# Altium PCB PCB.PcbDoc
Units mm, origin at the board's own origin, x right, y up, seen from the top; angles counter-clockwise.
Board outline 41 x 25.36 mm, 2 copper layers (TOP, BOTTOM), stack 1.586 mm thick; 29 components, 6 nets, 59 pads, 21 vias.
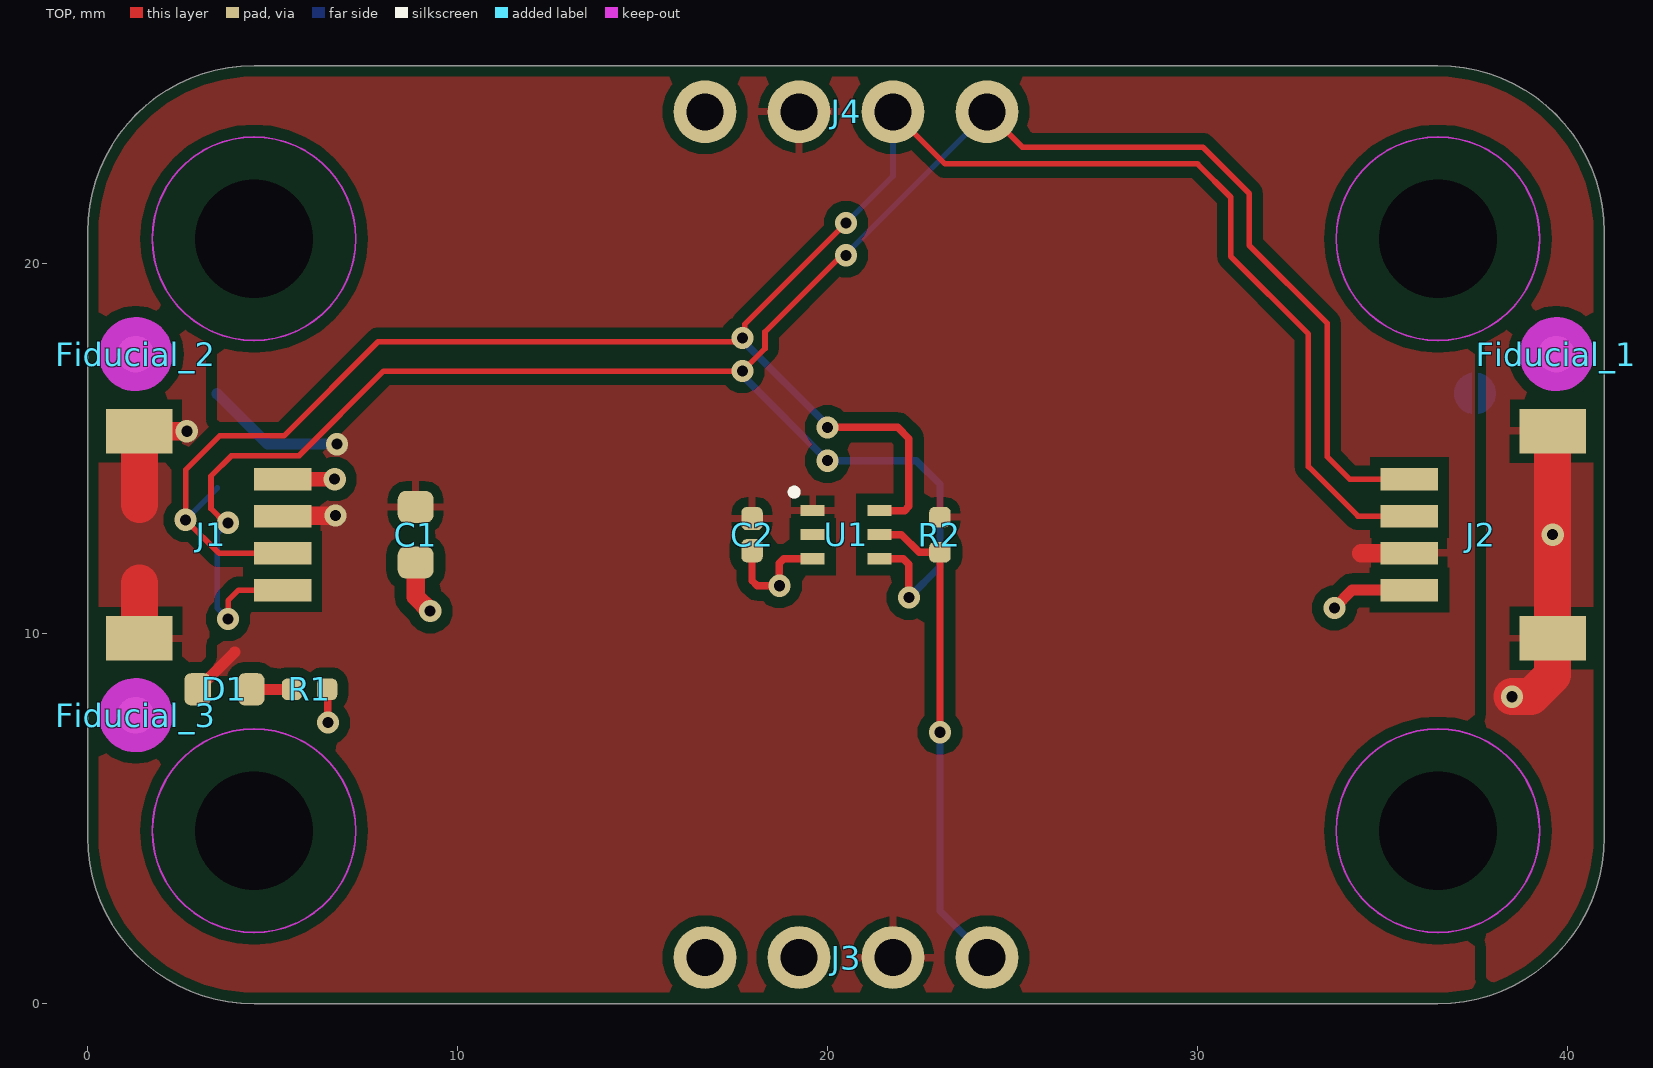
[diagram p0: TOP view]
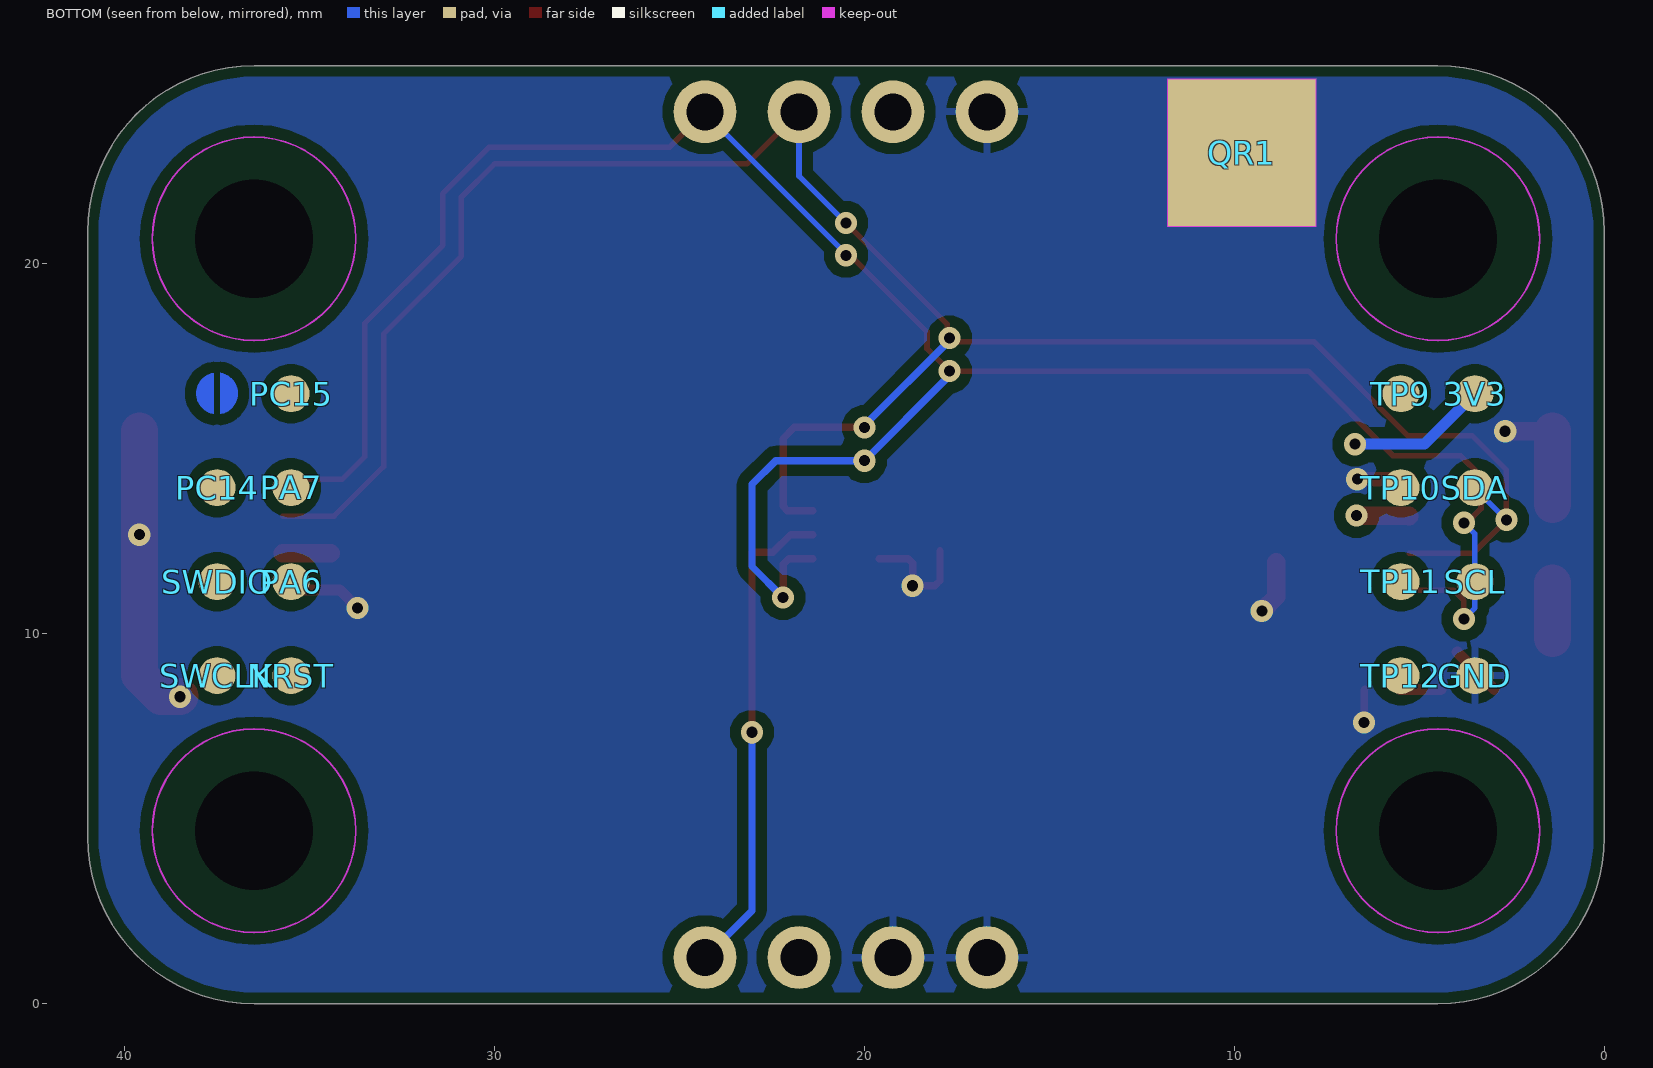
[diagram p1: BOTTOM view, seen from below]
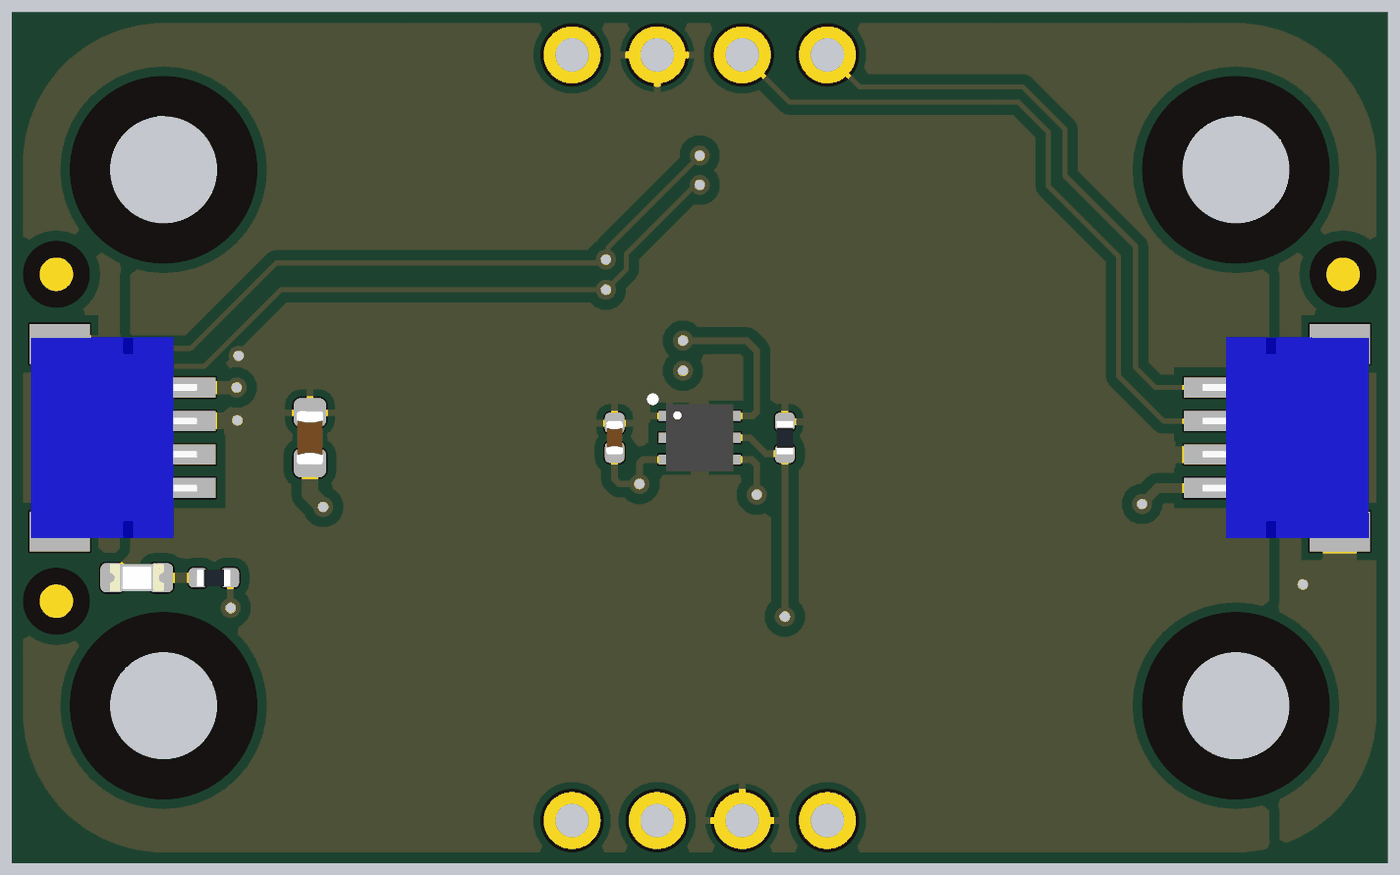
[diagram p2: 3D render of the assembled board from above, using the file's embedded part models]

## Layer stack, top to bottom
Top Solder: solder mask 0.01, Solder Resist, Dk 3.5
TOP: signal copper 0.018
Dielectric: core 1.55, FR-4, Dk 4.8
BOTTOM: signal copper 0.018
Bottom Solder: solder mask 0.01, Solder Resist, Dk 3.5

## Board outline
0,4.5 ccw(c4.5,4.5) 4.5,0 36.5,0 ccw(c36.5,4.5) 41,4.5 41,20.86 ccw(c36.5,20.86) 36.5,25.36 4.5,25.36 ccw(c4.5,20.86) 0,20.86

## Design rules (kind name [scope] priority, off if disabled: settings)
BoardOutlineClearance Mousebites [(ObjectKind = 'Pad') And (Name = 'Free-MOUSEBITE')] p1: gap=0 ignorepadtopadclearanceinfootprint=FALSE
BoardOutlineClearance Silks [(OnLayer('Top Overlay') OR OnLayer('Bottom Overlay'))] p2: gap=0 ignorepadtopadclearanceinfootprint=FALSE
BoardOutlineClearance [All] p3: gap=0.3 ignorepadtopadclearanceinfootprint=FALSE
Clearance COPPER_0.3mm [All] p1: gap=0.127 ignorepadtopadclearanceinfootprint=FALSE except(0.3: Arc-Fill Arc-Poly Arc-Region Track-Fill Track-Poly Track-Region SMDPad-Fill SMDPad-Poly SMDPad-Region THPad-Fill THPad-Poly THPad-Region Via-Fill Via-Poly Via-Region Fill-Fill Fill-Poly Fill-Region Poly-Poly Poly-Region Region-Region)
Clearance "Generic clearance 0.15mm" [All] p2: gap=0.127 ignorepadtopadclearanceinfootprint=FALSE
ComponentClearance [All] p1: gap=0.2 collisioncheckmode=3 verticalgap=0 showdistances=TRUE
DiffPairsRouting USB [InDifferentialPairClass('USB')] p1: maxlimit=0.15 minlimit=0.15 mostfreqgap=0.15 toplayer_minwidth=0.15 toplayer_maxwidth=0.21 toplayer_prefwidth=0.2 bottomlayer_minwidth=0.15 bottomlayer_maxwidth=0.21 bottomlayer_prefwidth=0.2 impedanceprofiledriven=TRUE impedanceprofileid={E6B00C31-4C8E-439C-824F-D2B2CDC26F9C} impedanceprofilevalue=90.000000 maxuncoupledlength=12.7
Height [All] p1: minheight=0 maxheight=30 prefheight=12.7
HoleSize [All] p1: absolutevalues=TRUE maxlimit=30 minlimit=0.3 maxpercent=80.000 minpercent=20.000
HoleToHoleClearance [All] p1: gap=0.25 allowstackedmicrovias=FALSE
MinimumAnnularRing [All] p1: minimumring=0.15
NetAntennae NetAntennae_1 [WithinRoom('SHORTROOM')] p1: netantennaetolerance=3
NetAntennae [All] p2: netantennaetolerance=0
PlaneConnect [All] p1: pad.planeconnectstyle=Relief pad.reliefexpansion=0.508 pad.reliefentries=4 pad.reliefconductorwidth=0.254 pad.reliefairgap=0.254 via.planeconnectstyle=Direct via.reliefexpansion=0.508 via.reliefentries=4 via.reliefconductorwidth=0.254 via.reliefairgap=0.254
PolygonConnect PolygonConnect_QR [(ObjectKind = 'Pad') And (Name = 'QR1-PAD')] p1: connectstyle=Direct reliefconductorwidth=0.254 reliefentries=4 polygonreliefangle="90 Angle" airgapwidth=0.254
PolygonConnect [All] p2: thpad.connectstyle=Relief thpad.reliefconductorwidth=0.2 thpad.reliefentries=4 thpad.polygonreliefangle="90 Angle" thpad.airgapwidth=0.254 smdpad.connectstyle=Relief smdpad.reliefconductorwidth=0.2 smdpad.reliefentries=4 smdpad.polygonreliefangle="90 Angle" smdpad.airgapwidth=0.254 via.connectstyle=Direct via.reliefconductorwidth=0.254 via.reliefentries=4 via.polygonreliefangle="90 Angle" via.airgapwidth=0.254
RoomDefinition SHORTROOM [False vs False] p1: confinementstyle=ConfineIn formatcopy=TRUE lockcomponents=FALSE outline 21.37,5.005 22.17,5.005 22.17,2.905 21.37,2.905
RoomDefinition K36 [False vs False] p2: confinementstyle=ConfineIn formatcopy=TRUE lockcomponents=FALSE outline 12.1,25.6 15.4,25.6 15.4,22.8 12.1,22.8
RoomDefinition U_MICROCONTROLLER [InComponentClass('U_MICROCONTROLLER')] p3: confinementstyle=ConfineIn formatcopy=TRUE lockcomponents=FALSE outline -26.2,-22.88 24.6,-22.88 24.6,2.52 -26.2,2.52
RoomDefinition TOP [InComponentClass('TOP')] p4: confinementstyle=ConfineIn formatcopy=TRUE lockcomponents=FALSE outline -26.2,-22.88 24.6,-22.88 24.6,2.52 -26.2,2.52
RoutingVias StandardVias [All] p1: holewidth=0.3 width=0.6 viastyle="Through Hole" minholewidth=0.3 minwidth=0.6 maxholewidth=0.3 maxwidth=0.6
SMDToCorner [All] p1: distance=39370
ShortCircuit Shortjumper [WithinRoom('SHORTROOM') vs WithinRoom('SHORTROOM')] p1: allowed=TRUE
ShortCircuit [All] p2: allowed=FALSE
SilkToSilkClearance [All] p1: silktosilkclearance=0.2
SilkToSolderMaskClearance [IsPad] p1: minsilkscreentomaskgap=0.15 clearancetoexposedcopper=TRUE
SolderMaskExpansion VIAtented [IsVia] p1: expansion=0.102 istentingtop=TRUE
SolderMaskExpansion [All] p2: expansion=0.05 istentingtop=FALSE
SupplyNets "Schematic Supply Nets_1" [InNet('GND')] p1: voltage=0.000
SupplyNets "Schematic Supply Nets" [InNet('+3V3')] p2: voltage=0.000
UnConnectedPin [All] p1:
UnRoutedNet [NOT WithinRoom('K36')] p1: checkbadconnections=TRUE
ViasUnderSMD [All] p1: allowed=FALSE
Width StandardTraces [All] p1: maxlimit=5 minlimit=0.15 preferedwidth=0.15 minimp=50.000000 maximp=50.000000 favimp=50.000000
19 further rules are at their usual default settings.

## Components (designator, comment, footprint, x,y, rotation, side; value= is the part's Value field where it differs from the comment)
3V3 "Test point 1.00mm" TP-1.00MM 3.5,16.49 r90 bottom
C1 "GRM188R61C475KAAJD" CAP-0603 8.868,12.68 r90 top value=4.7µF
C2 "0402B104K160CT" CAP-0402 17.96,12.68 r270 top value=100nF
D1 "HSMG-C190" LEDC1608X80N-AK 3.7,8.5 r180 top
Fiducial_1 "Fiducial mark 1mm" "Fiducial mark 1mm-Footprint-1" 39.7,17.56 r270 top
Fiducial_2 "Fiducial mark 1mm" "Fiducial mark 1mm-Footprint-1" 1.3,17.56 r270 top
Fiducial_3 "Fiducial mark 1mm" "Fiducial mark 1mm-Footprint-1" 1.3,7.8 r270 top
GND "Test point 1.00mm" TP-1.00MM 3.5,8.87 r90 bottom
J1 "SM04B-SRSS-TB(LF)(SN)" SM04B-SRSS-TB(LF)(SN)-Footprint-1 3.337,12.68 r90 top locked
J2 "SM04B-SRSS-TB(LF)(SN)" SM04B-SRSS-TB(LF)(SN)-Footprint-1 37.663,12.68 r270 top locked
J3 "HEADER TH 2.54mm VERT. 1x004POS" "PIN HEADER 2.54mm VERT. 1x4POS-Footprint-1" 20.5,1.25 r0 top
J4 "HEADER TH 2.54mm VERT. 1x004POS" "PIN HEADER 2.54mm VERT. 1x4POS-Footprint-1" 20.5,24.11 r0 top
NRST "Test point 1.00mm" TP-1.00MM 35.5,8.87 r180 bottom
PA6 "Test point 1.00mm" TP-1.00MM 35.5,11.41 r180 bottom
PA7 "Test point 1.00mm" TP-1.00MM 35.5,13.95 r180 bottom
PC14 "Test point 1.00mm" TP-1.00MM 37.5,13.95 r180 bottom
PC15 "Test point 1.00mm" TP-1.00MM 35.5,16.49 r180 bottom
QR1 "QR CODE 4x4mm" "QR CODE 4x4mm" 9.8,23 r180 bottom
R1 "CRCW04021K00FKEDC" RES-0402 6,8.5 r180 top value=1k
R2 "CRCW040210K0FKED" RES-0402 23.04,12.68 r270 top value=10k
SCL "Test point 1.00mm" TP-1.00MM 3.5,11.41 r90 bottom
SDA "Test point 1.00mm" TP-1.00MM 3.5,13.95 r90 bottom
SWCLK "Test point 1.00mm" TP-1.00MM 37.5,8.87 r180 bottom
SWDIO "Test point 1.00mm" TP-1.00MM 37.5,11.41 r180 bottom
TP9 "Test point 1.00mm" TP-1.00MM 5.5,16.49 r0 bottom
TP10 "Test point 1.00mm" TP-1.00MM 5.5,13.95 r0 bottom
TP11 "Test point 1.00mm" TP-1.00MM 5.5,11.41 r0 bottom
TP12 "Test point 1.00mm" TP-1.00MM 5.5,8.87 r0 bottom
U1 "LTR-381RGB-01" SON65P200X70-6N 20.5,12.68 r0 top

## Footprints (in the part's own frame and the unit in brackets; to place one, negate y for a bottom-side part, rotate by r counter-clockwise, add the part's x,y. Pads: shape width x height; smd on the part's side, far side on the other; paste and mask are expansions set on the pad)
CAP-0402 [mm] "Chip Capacitor, 2-Leads, Body  0402 (in) 1005 (mm), IPC Medium Density"
  rrect52% 0.63x0.58 smd mask+0.05: 1(-0.435,0) 2(0.435,0)
  body extent -0.5,-0.25 0.5,0.25, height 0.5
CAP-0603 [mm] "Chip Capacitor, Body 0603 imperial,1.6x0.8mm, IPC High Density"
  rrect51% 0.87x0.97 smd mask+0.05: 1(-0.75,0) 2(0.75,0)
  body extent -0.8,-0.4 0.8,0.4, height 0.8
"Fiducial mark 1mm-Footprint-1" [mm]
  round 1 smd paste-10 mask+0.5: 1(0,0)
  TOP keep-out circle w1: c0,0 r0.5
LEDC1608X80N-AK [mm]
  rrect50% 0.72x0.87 smd: A(0.725,0) C(-0.725,0)
  body extent -0.8,-0.4 0.8,0.4, height 0.79
"PIN HEADER 2.54mm VERT. 1x4POS-Footprint-1" [mm]
  round 1.7 hole 1 mask+0.1: 1(-3.81,0) 2(-1.27,0) 3(1.27,0) 4(3.81,0)
"QR CODE 4x4mm" [mm]
  rect 4x4 smd paste-2539.97 mask+0.1: PAD(0,0)
  TOP keep-out region: -2,2 2,2 2,-2 -2,-2
RES-0402 [mm] "Chip Resistor, 2-Leads, Body  0402 (in) 1005 (mm), IPC Medium Density"
  rrect51% 0.55x0.58 smd mask+0.05: 1(-0.475,0) 2(0.475,0)
  body extent -0.5,-0.25 0.5,0.25, height 0.34
SM04B-SRSS-TB(LF)(SN)-Footprint-1 [mm]
  rect 0.6x1.55 smd mask+0.05: 1(1.5,-1.937) 2(0.5,-1.937) 3(-0.5,-1.937) 4(-1.5,-1.937)
  rect 1.2x1.8 smd mask+0.05: FIX(-2.8,1.938) FIX(2.8,1.938)
  body extent -3,-2.16 3,2.8, height 2.98
SON65P200X70-6N [mm] "SON, 6-Leads, Body 2,00x2,00mm, Pitch 0,65mm, IPC Medium Density"
  rect 0.65x0.3 smd mask+0.05: 1(-0.9,0.65) 2(-0.9,0) 3(-0.9,-0.65) 4(0.9,-0.65) 5(0.9,0) 6(0.9,0.65)
  silkscreen extent -1.45,1.1 -1.35,1.2, body extent -1,-1 1,1, height 0.7
TP-1.00MM [mm]
  rrect100% 1x1 smd paste-2.54: X(0,0)

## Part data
3V3 GND NRST PA6 PA7 PC14 PC15 SCL SDA SWCLK SWDIO TP9 TP10 TP11 TP12: library part UT0013-A.6, Manufacturer="This is not a component"
C1: library part C0054-A.16, "CAP CHIP 0603 4.7uF 10% 16V X5R", Case Code (Imperial)=0603, Dielectric=X5R, Manufacturer=Murata, Manufacturer 3="Samsung Electro-Mechanics", Part number 2=GRM188R61C475KE11D, Part number 3=CL10A475KO8NNNC, Tolerance=10%, Voltage=16V
C2: library part C0012-A.15, "CAP CHIP 0402 100nF 10% 16V X7R", Case Code (Imperial)=0402, Dielectric=X7R, Manufacturer=Walsin, Tolerance=10%, Voltage=16V
D1: library part L0009-A.5, "LED SMD 0603 GREEN/568 15mcd 120^", Manufacturer=Broadcom
Fiducial_1 Fiducial_2 Fiducial_3: library part UT0023-A.7, "Fiducial mark 1mm clearance 2mm"
J1 J2: library part J0005-A.2, "CONN JST 4POS SIDE 1MM TIN QWIIC", Manufacturer=JST
J3 J4: library part J0162-A.6
QR1: library part QR-0001-A.5, "QR CODE 4x4mm on layer 34 (This is not a component)", Manufacturer="This is not a component"
R1: library part R0007-A.24, "RES CHIP 0402 1k 1% 1/16W", Case Code (Imperial)=0402, Manufacturer=Vishay, Power=62.5mW, Temperature Coefficient=100ppm, Tolerance=1%
R2: library part R0003-A.24, "RES CHIP 0402 10k 1% 1/16W", Case Code (Imperial)=0402, Manufacturer=Vishay, Power=62.5mW, Temperature Coefficient=100ppm, Tolerance=1%
U1: library part U0407-A.2, "IC light + RGB sensor , I2C, Vdd 1.7V to 3.6V, DFN 2x2mm", Manufacturer=Liteon

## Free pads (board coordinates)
  round 3 hole 3.2 unplated paste-2539.97 mask+1.3: MH(4.5,4.68) MH(4.5,20.68) MH(36.5,4.68) MH(36.5,20.68)

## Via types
v1: diameter 0.6, hole 0.3, TOP to BOTTOM, tented both sides, 21 vias

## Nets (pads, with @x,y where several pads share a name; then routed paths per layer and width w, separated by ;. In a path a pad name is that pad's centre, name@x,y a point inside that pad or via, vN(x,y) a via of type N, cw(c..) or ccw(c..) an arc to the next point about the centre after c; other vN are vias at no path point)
+3V3: 3V3.X C1.2 C2.1 D1.A J1.2 J2.2 J3.3 J4.2 R2.1 U1.1 | length 8
  TOP w0.3: D1.A 3.98,9.505
  TOP w0.5: J1.2 5.284,13.19 6.69,13.19 v1(6.7,13.2) ; 34.42,12.18 J2.2
  BOTTOM w0.3: 3V3.X 4.864,15.126 v1(6.741,15.126)
GND: C1.1 C2.2 GND.X J1.1 J1.FIX J2.1 J2.FIX J3.1 J3.2 J4.1 QR1.PAD R1.1 U1.3 | length 21.9
  TOP w0.2: R1.1 6.488,8.488 6.488,7.612 v1(6.5,7.6) ; C2.2 17.96,11.44 18.1,11.3 v1(18.7,11.3) 18.7,11.913 18.817,12.03 U1.3
  TOP w0.3: v1(33.7,10.7) 34.18,11.18 J2.1 J2.1@35.72,11.185
  TOP w0.4: J1.1 v1(6.68,14.18)
  TOP w0.5: J1.FIX@1.399,15.48 2.678,15.48 v1(2.683,15.475) ; C1.1 8.868,11.007 v1(9.261,10.613)
  TOP w1: J1.FIX@1.399,9.88 1.399,11.379 ; 1.399,13.499 J1.FIX@1.399,15.48 ; v1(38.5,8.3) 39.015,8.3 39.601,8.886 J2.FIX@39.601,9.88 ; J2.FIX@39.6,9.881 J2.FIX@39.6,15.48
  other v1: 39.6,12.68
INT_1: J3.4 R2.2 U1.5 | length 13.3
  TOP w0.2: U1.5 22,12.68 22.475,12.205 R2.2 v1(23.04,7.34)
  BOTTOM w0.2: v1(23.04,7.34) 23.04,2.52 J3.4
NetD1_C: D1.C R1.2 | length 1.1
  TOP w0.3: D1.C R1.2
SCL_1: J1.4 J2.4 J4.4 SCL.X U1.4 | length 62.1
  TOP w0.15: v1(3.8,10.4) 3.8,10.9 4.08,11.18 J1.4 ; v1(3.8,13) 3.723,13 3.337,13.386 3.337,14.262 3.888,14.813 5.718,14.813 8.005,17.1 v1(17.7,17.1) 18.31,17.71 18.31,18.162 20.378,20.23 v1(20.5,20.23) ; J4.4 25.263,23.157 30.143,23.157 31.4,21.9 31.4,20.5 33.502,18.398 33.502,14.788 34.11,14.18 J2.4
  TOP w0.2: U1.4 22.05,12.03 22.2,11.88 v1(22.2,10.98)
  BOTTOM w0.15: v1(3.8,10.4) 3.5,10.7 3.5,12.7 v1(3.8,13) ; v1(20.5,20.23) 20.5,20.265 24.31,24.075 J4.4
  BOTTOM w0.2: v1(17.7,17.1) 17.777,17.023 17.777,16.904 v1(20,14.68) 22.4,14.68 23.04,14.04 23.04,11.82 v1(22.2,10.98)
SDA_1: J1.3 J2.3 J4.3 SDA.X U1.6 | length 59.8
  TOP w0.15: 2.65,14.44 v1(2.65,13.082) 3.554,12.178 3.895,12.178 3.897,12.18 J1.3 ; 2.66,14.44 3.569,15.349 5.306,15.349 7.857,17.9 v1@17.7,17.9 ; v1@17.7,17.991 17.768,18.058 17.768,18.373 v1(20.5,21.105) ; J4.3 23.18,22.7 30,22.7 30.9,21.8 30.9,20.2 33,18.1 33,14.518 34.338,13.18 J2.3
  TOP w0.2: v1(20,15.58) 21.9,15.58 22.2,15.28 22.2,13.447 22.083,13.33 U1.6
  BOTTOM w0.15: v1(2.65,13.082) 3.5,13.932 SDA.X ; v1(20.5,21.105) 21.77,22.375 J4.3
  BOTTOM w0.2: v1(17.7,17.998) 17.7,17.939 20,15.639 v1(20,15.58)
pads on no net: Fiducial_1.1 Fiducial_2.1 Fiducial_3.1 NRST.X PA6.X PA7.X PC14.X PC15.X SWCLK.X SWDIO.X TP9.X TP10.X TP11.X TP12.X U1.2

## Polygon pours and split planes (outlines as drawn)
GND on TOP "NONET_L04_P-001" (solid, remove dead copper, pour order 13): 0,4.5 ccw(c4.5,4.5) 4.5,0 36.5,0 ccw(c36.5,4.5) 41,4.5 41,20.86 ccw(c36.5,20.86) 36.5,25.36 4.5,25.36 ccw(c4.5,20.86) 0,20.86
+3V3 on TOP "NONET_L04_P-001" (solid, remove dead copper, pour order 12): 0,4.5 ccw(c4.5,4.5) 4.5,0 36.5,0 ccw(c36.5,4.5) 41,4.5 41,20.86 ccw(c36.5,20.86) 36.5,25.36 4.5,25.36 ccw(c4.5,20.86) 0,20.86
GND on TOP "NONET_L04_P-001" (solid, remove dead copper, pour order 11): 0,25.36 0,0 3.2,0 3.2,25.36
GND on TOP "NONET_L04_P-001" (solid, remove dead copper, pour order 10): 41,25.36 41,0 37.8,0 37.8,25.36
GND on BOTTOM "NONET_L04_P-001" (solid, remove dead copper, pour order 14): 0,4.5 ccw(c4.5,4.5) 4.5,0 36.5,0 ccw(c36.5,4.5) 41,4.5 41,20.86 ccw(c36.5,20.86) 36.5,25.36 4.5,25.36 ccw(c4.5,20.86) 0,20.86

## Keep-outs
Keep-Out Layer:
  circle w0.05: c36.5,4.68 r2.75
  circle w0.05: c36.5,20.68 r2.75
  circle w0.05: c4.5,4.68 r2.75
  circle w0.05: c4.5,20.68 r2.75

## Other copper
BOTTOM:
  region: 193 vertices and 0 holes, not listed, extent 36.945,15.949 37.415,17.054
  region: 197 vertices and 0 holes, not listed, extent 37.593,15.949 38.056,17.047

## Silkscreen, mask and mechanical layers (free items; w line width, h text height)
Route Tool Path:
  lines w2: -1,8.498 -1,16.86 ; 42,4.5 cw(c36.5,4.5) 36.5,-1 ; 42,8.498 42,16.86 ; -1,4.498 ccw(c4.5,4.5) 4.498,-1 ; -1,4.498 cw(c4.5,4.5) -1,4.5 ccw(c0,4.5) -1,4.498 ; -1,20.86 cw(c4.5,20.86) 4.5,26.36 ; -1,20.86 -1,20.86 ; 4.498,-1 ccw(c4.5,4.5) 4.5,-1 ; 4.498,-1 ccw(c4.5,0) 4.5,-1 ; 4.5,-1 36.5,-1 ; 4.5,26.36 36.5,26.36 ; 4.5,26.36 4.5,26.36 ; 36.5,-1 36.5,-1 ; 36.5,26.36 cw(c36.5,20.86) 36.502,26.36 ; 36.5,26.36 cw(c36.5,25.36) 36.502,26.36 ; 36.502,26.36 cw(c36.5,20.86) 42,20.863 ; 42,20.863 cw(c41,20.86) 42,20.86 ccw(c36.5,20.86) 42,20.863
Board:
  the board outline again, w0.05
